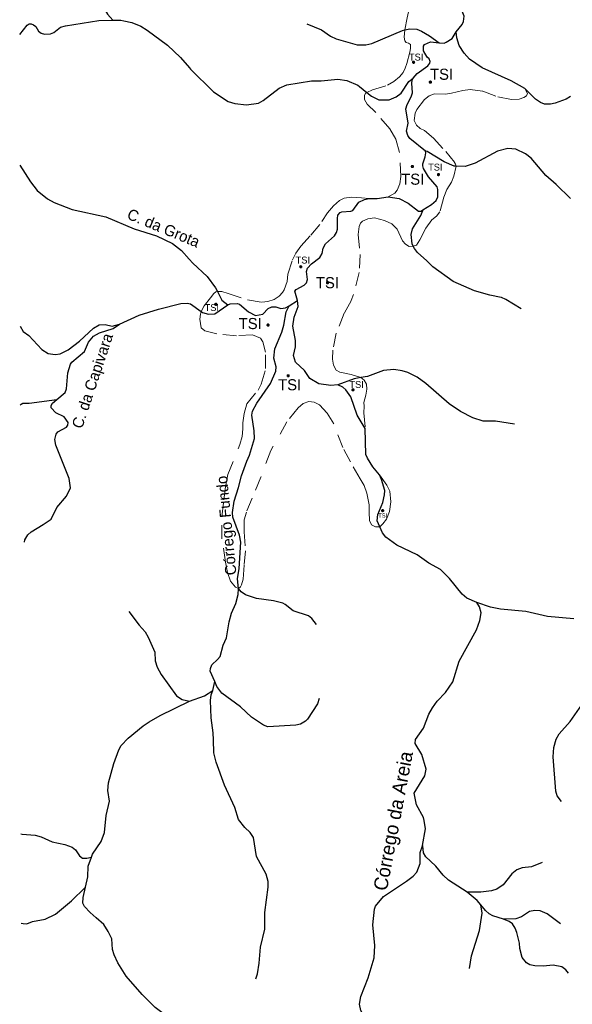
# Model space of a CAD drawing. Extents: x 473.9 to 500, y 7733.1 to 7760.8.
# Drawn here: x 473.91 to 477.9, y 7741.31 to 7748.41 of the extents above; entities that cross this region are included whole.
import ezdxf
from ezdxf.enums import TextEntityAlignment as Align

# ---------------------------------------------------------------- set-up
doc = ezdxf.new("R2010")
doc.units = 0
doc.header["$LTSCALE"] = 0.032
doc.header["$PDMODE"] = 32
doc.header["$PDSIZE"] = 0.016
doc.linetypes.add('SHORT_DASHED', pattern=[2.7, 1.5, -1.2])
doc.layers.add('21', color=7, linetype='SHORT_DASHED', lineweight=13)
doc.layers.add('7', color=7, linetype='Continuous', lineweight=25)
doc.layers.add('61', color=7, linetype='Continuous')

msp = doc.modelspace()

# ---------------------------------------------------------------- linework, layer by layer
at = {"layer": '21'}
for points in [[(476.688, 7748.3322), (476.7061, 7748.4194), (476.7376, 7748.5617), (476.7719, 7748.7144), (476.812, 7748.8386), (476.8731, 7748.9789), (476.9333, 7749.0811), (476.9689, 7749.1188), (477.0449, 7749.1653), (477.1611, 7749.2054), (477.4104, 7749.2751), (477.5096, 7749.3174), (477.554, 7749.3533), (477.5899, 7749.3913), (477.6275, 7749.4709)], [(476.4137, 7747.8823), (476.455, 7747.9001), (476.5629, 7747.9335), (476.6077, 7747.9602), (476.6507, 7747.9936), (476.6765, 7748.0261), (476.6898, 7748.0557), (476.7023, 7748.091), (476.7252, 7748.1722), (476.7283, 7748.199), (476.7283, 7748.2271), (476.7155, 7748.2379), (476.6979, 7748.2428), (476.6889, 7748.2543), (476.6841, 7748.2801), (476.688, 7748.3322)], [(476.5676, 7747.1297), (476.6155, 7747.1561), (476.6316, 7747.1774), (476.6514, 7747.224), (476.6589, 7747.2749), (476.6495, 7747.4486), (476.6235, 7747.5441), (476.5791, 7747.6184), (476.4781, 7747.7369), (476.4153, 7747.7983), (476.3977, 7747.8313), (476.3977, 7747.8609), (476.4034, 7747.8762), (476.4137, 7747.8823)], [(477.5536, 7747.9096), (477.5726, 7747.8746), (477.5654, 7747.8578), (477.5466, 7747.8458), (477.5143, 7747.8339), (477.4581, 7747.8305), (477.344, 7747.8544), (477.2487, 7747.8918), (477.1585, 7747.902), (477.1057, 7747.8969), (477.0239, 7747.877), (476.9822, 7747.8697), (476.9024, 7747.8729), (476.8631, 7747.8583), (476.8304, 7747.8309), (476.7748, 7747.758), (476.7625, 7747.7327), (476.7556, 7747.6785), (476.7729, 7747.6451), (476.7998, 7747.622), (476.829, 7747.6078), (476.8962, 7747.5513), (476.9831, 7747.4559), (477.0461, 7747.3776), (477.0546, 7747.364), (477.058, 7747.35)], [(477.058, 7747.35), (477.0427, 7747.2772), (477.026, 7747.2342), (476.9917, 7747.1831), (476.9687, 7747.1259), (476.9415, 7747.0218), (476.9168, 7746.9898), (476.8821, 7746.963), (476.8404, 7746.9034), (476.7975, 7746.8192), (476.772, 7746.7817), (476.749, 7746.7726)], [(475.3356, 7746.4461), (475.3668, 7746.4472), (475.4121, 7746.4326), (475.5529, 7746.3857), (475.6548, 7746.3695), (475.6985, 7746.3744), (475.7454, 7746.3889), (475.7807, 7746.4126), (475.805, 7746.4398), (475.8181, 7746.4588), (475.8393, 7746.5197), (475.8447, 7746.5724), (475.8765, 7746.6753), (475.9024, 7746.7222), (475.9364, 7746.774), (476.0108, 7746.8533), (476.0901, 7746.9504), (476.1305, 7747.0135), (476.1726, 7747.0652), (476.2163, 7747.1025), (476.2502, 7747.1186), (476.3036, 7747.1267), (476.3761, 7747.1215), (476.4309, 7747.1163)], [(476.749, 7746.7726), (476.7192, 7746.7715), (476.6936, 7746.7868), (476.6717, 7746.8112), (476.6324, 7746.8965), (476.5934, 7746.9335), (476.5416, 7746.9578), (476.4686, 7746.9772), (476.4204, 7746.9694), (476.3836, 7746.9526), (476.3678, 7746.9382), (476.3577, 7746.9157), (476.3503, 7746.8582), (476.3662, 7746.7136), (476.3591, 7746.584), (476.3181, 7746.4241), (476.3017, 7746.3823), (476.3006, 7746.3804), (476.2502, 7746.2899), (476.1931, 7746.1449), (476.1675, 7746.024), (476.1658, 7745.9576), (476.1726, 7745.9151), (476.1914, 7745.8793), (476.2186, 7745.864), (476.3003, 7745.847), (476.3694, 7745.826)], [(475.2182, 7746.3028), (475.239, 7746.342), (475.2843, 7746.4003), (475.3086, 7746.4326), (475.3231, 7746.4439), (475.3356, 7746.4461)], [(475.4883, 7744.3047), (475.4655, 7744.3147), (475.4299, 7744.3584), (475.4089, 7744.4198), (475.3927, 7744.4959), (475.3684, 7744.6625), (475.3668, 7744.8227), (475.3814, 7744.9441), (475.3927, 7745.0379), (475.4105, 7745.1269), (475.4977, 7745.3437), (475.5135, 7745.4005), (475.5182, 7745.4555), (475.5189, 7745.5007), (475.5287, 7745.5678), (475.5468, 7745.6364), (475.6293, 7745.7347), (475.6521, 7745.7777), (475.6836, 7745.8904), (475.6829, 7746.0099), (475.662, 7746.0839), (475.6453, 7746.1091), (475.5897, 7746.1347), (475.4737, 7746.127), (475.3308, 7746.1418), (475.2455, 7746.1621), (475.2184, 7746.1834), (475.2096, 7746.2479), (475.2131, 7746.2821), (475.2182, 7746.3028)], [(476.3694, 7745.826), (476.3957, 7745.8061), (476.411, 7745.7789), (476.4144, 7745.7431), (476.4063, 7745.6988), (476.3922, 7745.647), (476.3946, 7745.6192), (476.3923, 7745.5711), (476.4025, 7745.4577)], [(476.5072, 7744.7496), (476.4774, 7744.7488), (476.4468, 7744.7641), (476.4331, 7744.7965), (476.4297, 7744.8543), (476.4297, 7744.9088), (476.4144, 7744.9923), (476.394, 7745.0484), (476.3667, 7745.0961), (476.2952, 7745.2187), (476.2416, 7745.3209), (476.1753, 7745.4914), (476.1274, 7745.5683), (476.072, 7745.6282), (476.0347, 7745.6491), (475.9943, 7745.6539), (475.9535, 7745.6384), (475.9188, 7745.607), (475.8358, 7745.5058), (475.7212, 7745.3001), (475.6484, 7745.1069), (475.5869, 7744.9565), (475.5444, 7744.856), (475.529, 7744.7999), (475.529, 7744.7488), (475.529, 7744.713), (475.5376, 7744.5768), (475.5286, 7744.4732), (475.5205, 7744.3713), (475.5092, 7744.3309), (475.5027, 7744.3163), (475.4883, 7744.3047)], [(476.5044, 7745.1251), (476.5591, 7745.0501), (476.5796, 7745.0076), (476.5864, 7744.931), (476.5779, 7744.8612), (476.5557, 7744.805), (476.5302, 7744.7709), (476.5072, 7744.7496)]]:
    msp.add_lwpolyline(points, dxfattribs=at)
for p in [(476.7511, 7748.0993), (476.8724, 7747.9564), (476.7425, 7747.3479), (476.9309, 7747.2895), (475.937, 7746.6248), (476.1297, 7746.51), (475.3243, 7746.3541), (475.701, 7746.2047), (475.8461, 7745.8388), (476.3138, 7745.7371), (476.5281, 7744.8667)]:
    msp.add_point(p, dxfattribs=at)
at = {"layer": '7'}
for p, q in [((475.8541, 7746.3431), (475.9142, 7746.3815)), ((475.3022, 7743.5705), (475.3159, 7743.6354))]:
    msp.add_line(p, q, dxfattribs=at)
for points in [[(477.0598, 7748.3191), (477.1014, 7748.372), (477.1112, 7748.3924), (477.1162, 7748.4327), (477.0763, 7748.5341), (477.082, 7748.5759), (477.0739, 7748.6491), (477.0778, 7748.6816), (477.1081, 7748.7106), (477.1561, 7748.7339), (477.1794, 7748.7533), (477.1959, 7748.7781), (477.2244, 7748.8682), (477.2903, 7748.9318), (477.3071, 7748.9735), (477.3259, 7748.9989), (477.3517, 7749.0202), (477.3885, 7749.0348), (477.4395, 7749.0451), (477.5553, 7749.0548), (477.6476, 7749.0748), (477.6995, 7749.1031)], [(474.1664, 7748.7837), (474.3012, 7748.6642), (474.4178, 7748.5968), (474.4604, 7748.5629), (474.4932, 7748.5261), (474.541, 7748.4453), (474.5797, 7748.4041)], [(473.908, 7748.2996), (473.9616, 7748.3662), (473.9768, 7748.3763), (473.9914, 7748.3761), (474.0074, 7748.3697), (474.0242, 7748.3561), (474.0447, 7748.3237), (474.0634, 7748.3084), (474.0877, 7748.302), (474.1311, 7748.3055), (474.1548, 7748.3144), (474.2035, 7748.3516), (474.2378, 7748.3622), (474.4797, 7748.4014), (474.5797, 7748.4041)], [(474.5797, 7748.4041), (474.6384, 7748.4037), (474.66, 7748.3986), (474.7173, 7748.3851), (474.7834, 7748.3591), (474.8287, 7748.3317), (474.9743, 7748.2215), (475.0687, 7748.1326), (475.1334, 7748.0584), (475.14, 7748.0508), (475.3081, 7747.8861), (475.4123, 7747.817), (475.4616, 7747.801), (475.5446, 7747.7919), (475.6314, 7747.8041), (475.6665, 7747.8246), (475.7804, 7747.9137), (475.8366, 7747.9373), (476.0155, 7747.9667), (476.084, 7747.9652), (476.2041, 7747.9772), (476.2702, 7747.9676), (476.349, 7747.9339), (476.3611, 7747.9242), (476.4137, 7747.8823)], [(475.9815, 7748.3774), (476.0861, 7748.3339), (476.1524, 7748.2876), (476.193, 7748.2674), (476.3439, 7748.2245), (476.3902, 7748.2249), (476.4055, 7748.225), (476.4496, 7748.2344), (476.6718, 7748.3285), (476.688, 7748.3322)], [(476.688, 7748.3322), (476.725, 7748.3405), (476.7738, 7748.3371), (476.8088, 7748.3226), (476.8665, 7748.29), (476.9349, 7748.239)], [(476.9349, 7748.239), (476.9711, 7748.2382), (476.9853, 7748.2432), (477.0287, 7748.2711), (477.0598, 7748.3191)], [(477.5536, 7747.9096), (477.4555, 7747.966), (477.2457, 7748.0604), (477.1551, 7748.1229), (477.1152, 7748.1658), (477.0791, 7748.2202), (477.0631, 7748.2752), (477.0598, 7748.3191)], [(476.748, 7747.9852), (476.7761, 7748.0182), (476.8538, 7748.074), (476.8678, 7748.0927), (476.8709, 7748.1057), (476.8631, 7748.1246), (476.8489, 7748.1365), (476.8239, 7748.1815), (476.8233, 7748.2143), (476.8304, 7748.2276), (476.8727, 7748.2475), (476.9349, 7748.239)], [(476.4137, 7747.8823), (476.4469, 7747.8558), (476.5009, 7747.8281), (476.5762, 7747.8284), (476.6257, 7747.8494), (476.6623, 7747.8763), (476.7158, 7747.96), (476.748, 7747.9852)], [(476.8366, 7747.4592), (476.7232, 7747.5508), (476.709, 7747.5712), (476.6991, 7747.6033), (476.7115, 7747.6599), (476.6945, 7747.7639), (476.7042, 7747.7951), (476.735, 7747.849), (476.7443, 7747.8801), (476.7393, 7747.9496), (476.7408, 7747.9713), (476.748, 7747.9852)], [(477.8851, 7747.8528), (477.8529, 7747.8344), (477.7727, 7747.8035), (477.7396, 7747.7969), (477.6967, 7747.7978), (477.6668, 7747.8091), (477.6312, 7747.833), (477.5608, 7747.9025), (477.5536, 7747.9096)], [(476.8192, 7747.0345), (476.8805, 7747.0735), (476.9138, 7747.1033), (476.9262, 7747.1279), (476.9275, 7747.181), (476.9204, 7747.2022), (476.8599, 7747.2731), (476.8239, 7747.3341), (476.8174, 7747.3515), (476.8182, 7747.3674), (476.836, 7747.4175), (476.8389, 7747.4454), (476.8366, 7747.4592)], [(477.058, 7747.35), (477.0446, 7747.3504), (476.9719, 7747.3825), (476.849, 7747.4569), (476.8366, 7747.4592)], [(477.8842, 7747.1171), (477.7807, 7747.2191), (477.7064, 7747.282), (477.6009, 7747.4077), (477.5597, 7747.44), (477.4889, 7747.4729), (477.4327, 7747.4776), (477.3572, 7747.4588), (477.1954, 7747.3709), (477.1227, 7747.3479), (477.058, 7747.35)], [(473.9095, 7747.3586), (473.9864, 7747.2368), (474.0337, 7747.1753), (474.1087, 7747.1146), (474.1573, 7747.0887), (474.286, 7747.0382), (474.5297, 7746.9859), (474.7349, 7746.8994), (474.8965, 7746.8473), (475.0114, 7746.7931), (475.0761, 7746.7422), (475.1319, 7746.6798), (475.1584, 7746.6502), (475.2616, 7746.5543), (475.3221, 7746.472), (475.3356, 7746.4461)], [(475.9142, 7746.3815), (475.8946, 7746.4483), (475.9049, 7746.4616), (475.9615, 7746.4924), (475.9795, 7746.5083), (475.9862, 7746.5323), (475.9791, 7746.5901), (475.9851, 7746.6145), (476.0141, 7746.6454), (476.0741, 7746.6912), (476.0909, 7746.72), (476.0997, 7746.7596), (476.1154, 7746.7905), (476.1804, 7746.8482), (476.1959, 7746.8714), (476.201, 7746.8956), (476.2011, 7746.9724), (476.2055, 7746.996), (476.2212, 7747.0157), (476.234, 7747.0218), (476.2991, 7747.0255), (476.313, 7747.0313), (476.3554, 7747.0911), (476.3961, 7747.1091), (476.4309, 7747.1163)], [(476.4309, 7747.1163), (476.4879, 7747.1159), (476.5676, 7747.1297)], [(476.5676, 7747.1297), (476.6473, 7747.1167), (476.7126, 7747.084), (476.7863, 7747.0252), (476.8043, 7747.025), (476.8155, 7747.0321), (476.8192, 7747.0345)], [(476.749, 7746.7726), (476.7404, 7746.7895), (476.734, 7746.8568), (476.7429, 7746.8975), (476.8029, 7746.9937), (476.8172, 7747.0294), (476.8192, 7747.0345)], [(477.5289, 7746.3205), (477.4177, 7746.3892), (477.3852, 7746.4032), (477.3837, 7746.4035), (477.3026, 7746.419), (477.1915, 7746.4502), (477.0372, 7746.5195), (476.8913, 7746.6243), (476.8459, 7746.6668), (476.7796, 7746.7289), (476.7577, 7746.7556), (476.749, 7746.7726)], [(475.3356, 7746.4461), (475.368, 7746.3839), (475.4108, 7746.3495)], [(474.6294, 7746.2115), (474.7707, 7746.2747), (474.9094, 7746.3196), (475.0703, 7746.3591), (475.1166, 7746.3616), (475.1403, 7746.3566), (475.2182, 7746.3028)], [(475.4108, 7746.3495), (475.4274, 7746.3577), (475.479, 7746.361), (475.4956, 7746.3557), (475.5593, 7746.3003), (475.61, 7746.2742), (475.6634, 7746.2819), (475.7018, 7746.3231), (475.7292, 7746.3362), (475.7577, 7746.3352), (475.7938, 7746.3235), (475.8264, 7746.3281), (475.8541, 7746.3431)], [(476.2054, 7745.7734), (476.1528, 7745.7686), (476.0662, 7745.7815), (476.0028, 7745.8191), (475.9632, 7745.8779), (475.8978, 7745.9358), (475.8851, 7745.9851), (475.8983, 7746.0478), (475.8979, 7746.0928), (475.8799, 7746.1967), (475.8886, 7746.2622), (475.9173, 7746.339), (475.9142, 7746.3815)], [(475.2182, 7746.3028), (475.2284, 7746.2957), (475.2712, 7746.2831), (475.3166, 7746.2865), (475.4108, 7746.3495)], [(475.4883, 7744.3047), (475.4792, 7744.3744), (475.4932, 7744.4486), (475.5043, 7744.639), (475.494, 7744.6898), (475.4458, 7744.8194), (475.4437, 7744.8542), (475.4556, 7744.9338), (475.4887, 7745.034), (475.5082, 7745.1166), (475.5466, 7745.2233), (475.568, 7745.2666), (475.6029, 7745.3857), (475.6014, 7745.4427), (475.584, 7745.5548), (475.5881, 7745.5846), (475.6192, 7745.6407), (475.7173, 7745.7837), (475.7577, 7745.8731), (475.7598, 7745.9029), (475.7424, 7745.9656), (475.7502, 7746.0334), (475.7999, 7746.1521), (475.8156, 7746.2026), (475.8308, 7746.3003), (475.8541, 7746.3431)], [(473.9112, 7746.1974), (473.9334, 7746.158), (473.9731, 7746.1286), (474.0675, 7746.0276), (474.1139, 7745.9987), (474.1642, 7745.9911), (474.1997, 7745.9982), (474.2588, 7746.0264), (474.3406, 7746.0874), (474.4398, 7746.181), (474.4825, 7746.206), (474.5248, 7746.2092), (474.5755, 7746.1965), (474.6294, 7746.2115)], [(474.1753, 7745.6671), (474.2372, 7745.7188), (474.2468, 7745.7442), (474.2549, 7745.86), (474.2738, 7745.9232), (474.2835, 7745.938), (474.3766, 7746.0137), (474.4054, 7746.0806), (474.4406, 7746.1239), (474.4838, 7746.1482), (474.582, 7746.1809), (474.6294, 7746.2115)], [(477.4793, 7745.4901), (477.3419, 7745.5125), (477.2528, 7745.5126), (477.18, 7745.5348), (477.0906, 7745.582), (477.0076, 7745.6371), (476.84, 7745.7833), (476.777, 7745.8291), (476.709, 7745.862), (476.6684, 7745.8749), (476.6083, 7745.8838), (476.5338, 7745.8774), (476.4175, 7745.8345), (476.3694, 7745.826)], [(476.3694, 7745.826), (476.3213, 7745.8175), (476.2054, 7745.7734)], [(476.4025, 7745.4577), (476.3446, 7745.5547), (476.2986, 7745.686), (476.2618, 7745.7372), (476.2399, 7745.7573), (476.2054, 7745.7734)], [(473.9121, 7745.6283), (473.9195, 7745.6337), (473.9312, 7745.6423), (473.9765, 7745.6417), (474.1753, 7745.6671)], [(473.942, 7744.6393), (473.9461, 7744.656), (473.9673, 7744.6922), (473.9905, 7744.7127), (474.0787, 7744.7653), (474.1359, 7744.8059), (474.1764, 7744.8898), (474.2461, 7744.9696), (474.2756, 7745.0307), (474.2644, 7745.098), (474.1683, 7745.3382), (474.1618, 7745.3794), (474.1709, 7745.4169), (474.1845, 7745.4341), (474.2455, 7745.4688), (474.2547, 7745.4834), (474.2572, 7745.5021), (474.2291, 7745.5421), (474.1688, 7745.5723), (474.1346, 7745.6084), (474.1346, 7745.6255), (474.1438, 7745.6412), (474.1753, 7745.6671)], [(476.5044, 7745.1251), (476.4568, 7745.1828), (476.4181, 7745.2442), (476.4068, 7745.2714), (476.4025, 7745.4577)], [(476.5072, 7744.7496), (476.4884, 7744.7931), (476.4923, 7744.8392), (476.5301, 7744.924), (476.5413, 7744.9796), (476.5427, 7745.0127), (476.5207, 7745.0905), (476.5044, 7745.1251)], [(477.2072, 7744.2029), (477.1352, 7744.2354), (477.1024, 7744.2637), (477.0095, 7744.3767), (476.9449, 7744.441), (476.862, 7744.4888), (476.7769, 7744.5489), (476.6306, 7744.6175), (476.5506, 7744.676), (476.5261, 7744.7062), (476.5072, 7744.7496)], [(475.3159, 7743.6354), (475.2828, 7743.7081), (475.2848, 7743.7291), (475.2946, 7743.7555), (475.3367, 7743.7921), (475.3541, 7743.8157), (475.3773, 7743.8969), (475.4001, 7743.9495), (475.4192, 7744.0645), (475.4368, 7744.1281), (475.4686, 7744.1957), (475.4847, 7744.2622), (475.4883, 7744.3047)], [(476.0499, 7744.0466), (476.0167, 7744.089), (475.9935, 7744.1075), (475.8811, 7744.1429), (475.8255, 7744.1903), (475.8065, 7744.1999), (475.74, 7744.216), (475.6166, 7744.2325), (475.5383, 7744.2582), (475.5058, 7744.2808), (475.4883, 7744.3047)], [(476.8164, 7742.4524), (476.8373, 7742.5715), (476.8286, 7742.6314), (476.822, 7742.6544), (476.7722, 7742.7446), (476.7564, 7742.8294), (476.832, 7742.9547), (476.8413, 7743.0024), (476.8116, 7743.1082), (476.7638, 7743.1875), (476.7648, 7743.2151), (476.8223, 7743.2975), (476.8619, 7743.3992), (476.8882, 7743.4446), (476.9212, 7743.492), (476.9813, 7743.5559), (477.0338, 7743.6316), (477.0792, 7743.7808), (477.2066, 7744.0072), (477.2303, 7744.0737), (477.239, 7744.1294), (477.2281, 7744.1737), (477.2072, 7744.2029)], [(477.9091, 7744.0852), (477.7182, 7744.103), (477.5626, 7744.1399), (477.3779, 7744.1569), (477.3061, 7744.1712), (477.2072, 7744.2029)], [(474.6967, 7744.1403), (474.77, 7744.0407), (474.8134, 7743.9918), (474.8352, 7743.9549), (474.8831, 7743.8451), (474.8871, 7743.783), (474.9, 7743.7388), (474.9293, 7743.685), (475.0398, 7743.5305), (475.0812, 7743.5036), (475.1337, 7743.4931)], [(476.0698, 7743.5114), (476.0578, 7743.473), (475.9865, 7743.3639), (475.9715, 7743.348), (475.9347, 7743.3274), (475.902, 7743.3197), (475.7, 7743.3068), (475.6683, 7743.3196), (475.582, 7743.3763), (475.5019, 7743.4509), (475.3682, 7743.5509), (475.332, 7743.598), (475.3159, 7743.6354)], [(475.1337, 7743.4931), (475.2412, 7743.5322), (475.3022, 7743.5705)], [(475.6133, 7741.4903), (475.6243, 7741.5256), (475.6363, 7741.6046), (475.6457, 7741.7182), (475.6771, 7741.8476), (475.6772, 7741.9689), (475.7012, 7742.1523), (475.7005, 7742.1917), (475.6868, 7742.2452), (475.6164, 7742.3732), (475.5969, 7742.5095), (475.5729, 7742.5467), (475.5324, 7742.5825), (475.487, 7742.6385), (475.4607, 7742.7263), (475.3863, 7742.8881), (475.3274, 7743.0525), (475.31, 7743.1197), (475.3068, 7743.215), (475.3051, 7743.2635), (475.2895, 7743.3713), (475.286, 7743.4963), (475.2911, 7743.5382), (475.3022, 7743.5705)], [(477.82, 7742.7699), (477.7879, 7742.8106), (477.7771, 7742.8444), (477.7587, 7743.0924), (477.7627, 7743.1596), (477.7808, 7743.218), (477.8021, 7743.2574), (477.8806, 7743.3472), (477.9657, 7743.4661), (477.9848, 7743.514), (477.9926, 7743.5798)], [(474.4255, 7742.3677), (474.4346, 7742.3891), (474.4974, 7742.4803), (474.5207, 7742.5456), (474.5328, 7742.6691), (474.5571, 7742.7705), (474.5451, 7742.8487), (474.5496, 7742.9048), (474.5877, 7743.0431), (474.6227, 7743.1413), (474.6414, 7743.1724), (474.6904, 7743.227), (474.8003, 7743.3158), (474.8439, 7743.3428), (474.9209, 7743.3905), (475.1337, 7743.4931)], [(473.9168, 7742.5352), (473.925, 7742.5346), (474.0204, 7742.5274), (474.0627, 7742.5145), (474.1416, 7742.4773), (474.2336, 7742.4586), (474.2866, 7742.44), (474.31, 7742.4208), (474.3388, 7742.3769), (474.3619, 7742.3598), (474.393, 7742.3595), (474.4255, 7742.3677)], [(476.5367, 7741.0622), (476.4959, 7741.093), (476.4064, 7741.1932), (476.3697, 7741.2629), (476.3611, 7741.3075), (476.3698, 7741.363), (476.4227, 7741.4977), (476.4668, 7741.6417), (476.4725, 7741.7305), (476.4574, 7741.8809), (476.4683, 7741.9924), (476.477, 7742.0153), (476.5332, 7742.0846), (476.7005, 7742.1941), (476.7489, 7742.2298), (476.7736, 7742.2599), (476.7997, 7742.3225), (476.7985, 7742.4024), (476.8151, 7742.4488), (476.8164, 7742.4524)], [(477.1381, 7742.1156), (477.0038, 7742.2015), (476.9658, 7742.2372), (476.9124, 7742.3027), (476.9093, 7742.3065), (476.8403, 7742.3701), (476.8237, 7742.3992), (476.8169, 7742.4488), (476.8164, 7742.4524)], [(474.3836, 7742.1527), (474.4006, 7742.2254), (474.4032, 7742.3032), (474.4255, 7742.3677)], [(477.6797, 7742.329), (477.6021, 7742.2975), (477.5344, 7742.2902), (477.4962, 7742.276), (477.4609, 7742.2482), (477.3984, 7742.168), (477.3532, 7742.1364), (477.3147, 7742.1242), (477.2377, 7742.1146), (477.1381, 7742.1156)], [(473.9178, 7741.8913), (473.9326, 7741.89), (473.959, 7741.8876), (474.0018, 7741.9038), (474.0912, 7741.9201), (474.1663, 7741.9573), (474.2826, 7742.0534), (474.3809, 7742.1501), (474.3836, 7742.1527)], [(475.1163, 7741.1132), (475.1013, 7741.1306), (475.0542, 7741.1583), (474.8855, 7741.2827), (474.793, 7741.3767), (474.6769, 7741.509), (474.6163, 7741.6049), (474.5903, 7741.6637), (474.578, 7741.7029), (474.5723, 7741.7783), (474.547, 7741.8325), (474.5162, 7741.882), (474.4613, 7741.9302), (474.4173, 7741.9689), (474.3764, 7742.0123), (474.3649, 7742.0365), (474.3658, 7742.0767), (474.3836, 7742.1527)], [(477.2356, 7742.0233), (477.2093, 7742.0544), (477.1381, 7742.1156)], [(477.1539, 7741.5642), (477.1686, 7741.657), (477.2279, 7741.8382), (477.2463, 7741.9635), (477.2356, 7742.0233)], [(477.3993, 7741.9218), (477.323, 7741.9451), (477.2978, 7741.9602), (477.2698, 7741.9828), (477.2356, 7742.0233)], [(477.8129, 7741.8865), (477.7143, 7741.9603), (477.6656, 7741.9806), (477.6257, 7741.9831), (477.5868, 7741.976), (477.5303, 7741.9383), (477.4895, 7741.923), (477.3993, 7741.9218)], [(477.8685, 7741.5324), (477.851, 7741.5563), (477.8206, 7741.578), (477.7594, 7741.5903), (477.6859, 7741.5822), (477.6259, 7741.5849), (477.5893, 7741.5914), (477.5659, 7741.6058), (477.5362, 7741.6455), (477.5181, 7741.7093), (477.5157, 7741.7478), (477.4966, 7741.8245), (477.484, 7741.855), (477.4651, 7741.8876), (477.4415, 7741.9047), (477.3993, 7741.9218)]]:
    msp.add_lwpolyline(points, dxfattribs=at)

# ---------------------------------------------------------------- texts
at = {"layer": '61'}
for height, p in [(0.05, (476.7699, 7748.1119)), (0.08, (476.953, 7747.9729)), (0.05, (476.9081, 7747.3183)), (0.08, (476.7451, 7747.2165)), (0.05, (475.9518, 7746.6482)), (0.08, (476.1297, 7746.47)), (0.05, (475.2948, 7746.3056)), (0.08, (475.5721, 7746.1755)), (0.08, (475.8568, 7745.7343)), (0.05, (476.34, 7745.7511)), (0.03, (476.5281, 7744.8161))]:
    msp.add_text('TSI', height=height, dxfattribs=at).set_placement(p, align=Align.CENTER)
for s, height, rotation, p in [('C. da Grota', 0.08, 337.482, (474.9315, 7746.8679)), ('C. da Capivara', 0.08, 71.565, (474.4707, 7745.7901)), ('Córrego Fundo', 0.08, 95.481, (475.4392, 7744.7626)), ('Córrego da Areia', 0.1, 79.261, (476.6529, 7742.6201))]:
    msp.add_text(s, height=height, rotation=rotation, dxfattribs=at).set_placement(p, align=Align.CENTER)

doc.saveas('drawing.dxf')
